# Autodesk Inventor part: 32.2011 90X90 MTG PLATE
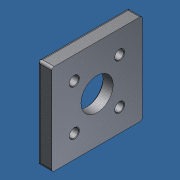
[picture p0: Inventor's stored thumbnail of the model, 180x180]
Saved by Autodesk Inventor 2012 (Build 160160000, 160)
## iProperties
Created: 2016-09
Part Number: 32.2011 90X90 MTG PLATE
Material: Aluminum-6061
Document SubType Name: Modeling
Designer: Admin
Density: 2.71 g/cm^3
Stock Number: 21.1059
Mass: 253.779 g
Surface Area: 219.524 cm^2
Volume: 93.6456 cm^3
Author: Admin
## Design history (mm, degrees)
feature "Base1"
body "Solid1"
